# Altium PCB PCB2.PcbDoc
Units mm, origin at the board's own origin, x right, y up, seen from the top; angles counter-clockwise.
Board outline 67.61 x 64.44 mm, 2 copper layers (Top Layer, Bottom Layer); 17 components, 18 nets, 58 pads, 0 vias.
Unrouted connection lines stored in the file: 2.
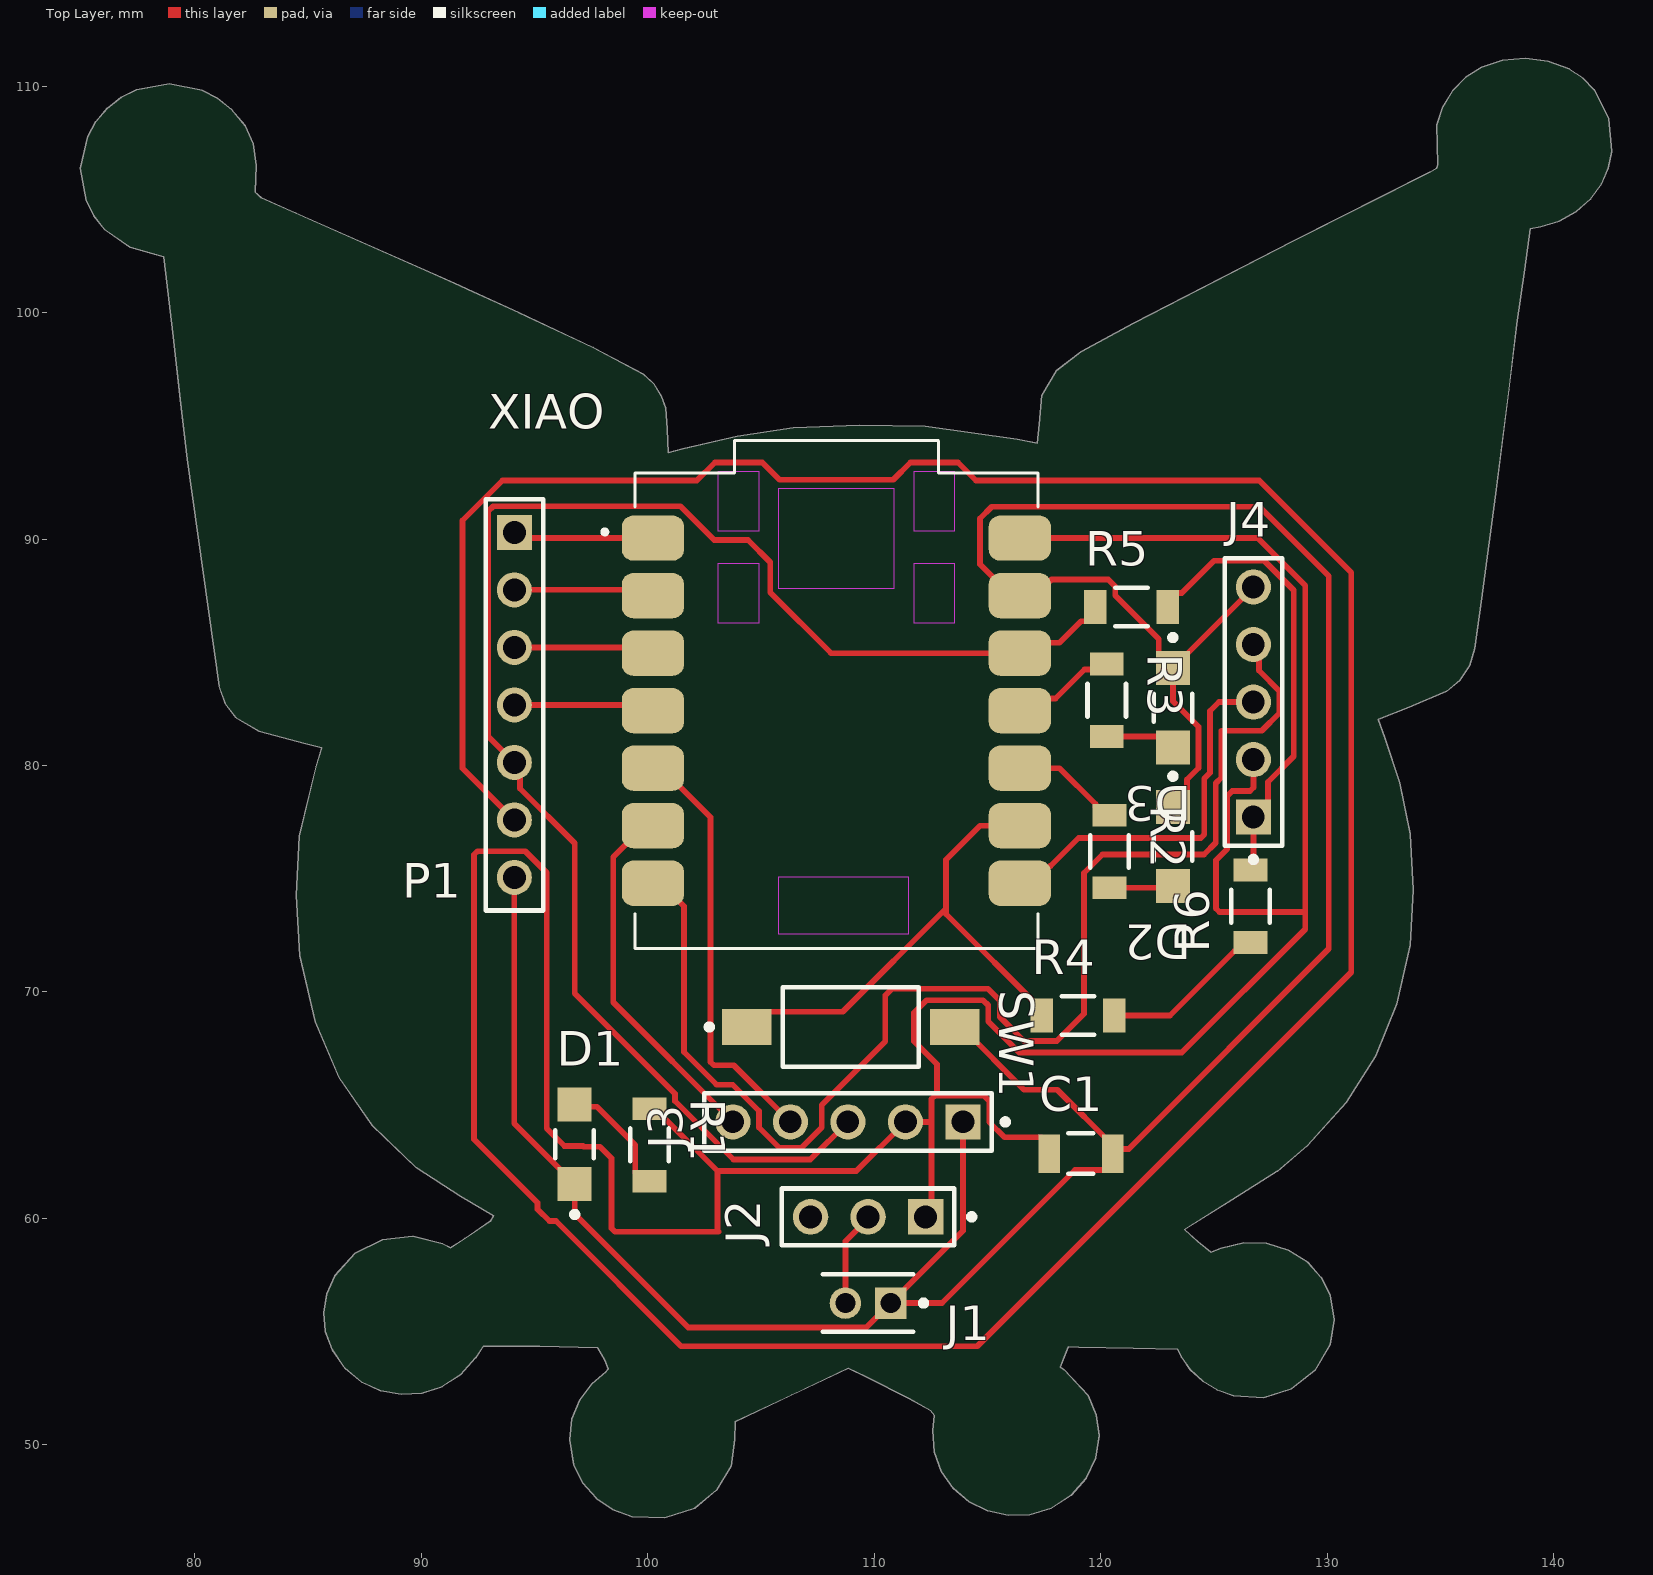
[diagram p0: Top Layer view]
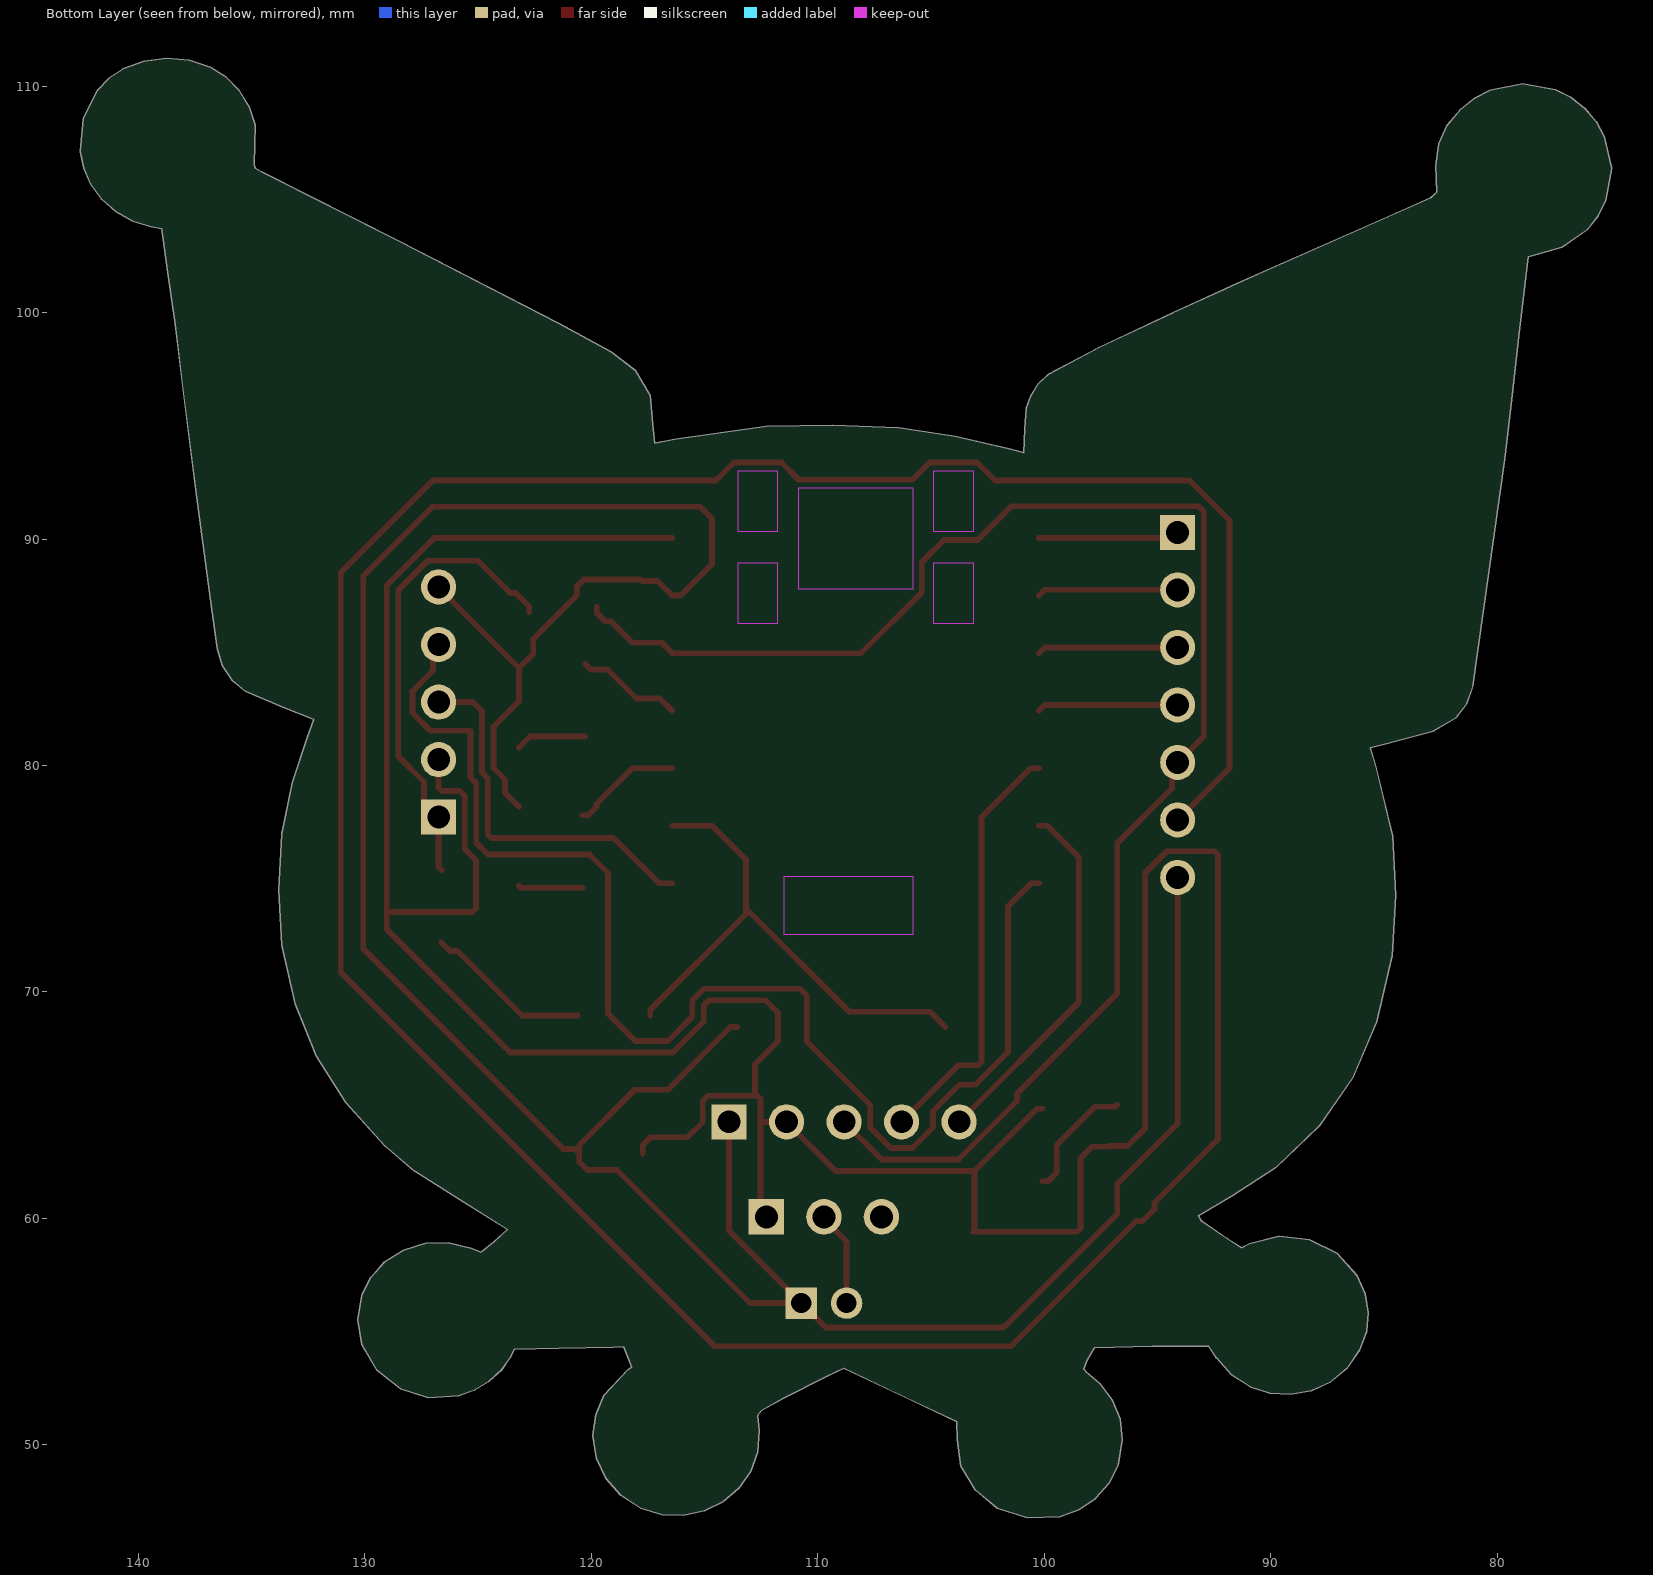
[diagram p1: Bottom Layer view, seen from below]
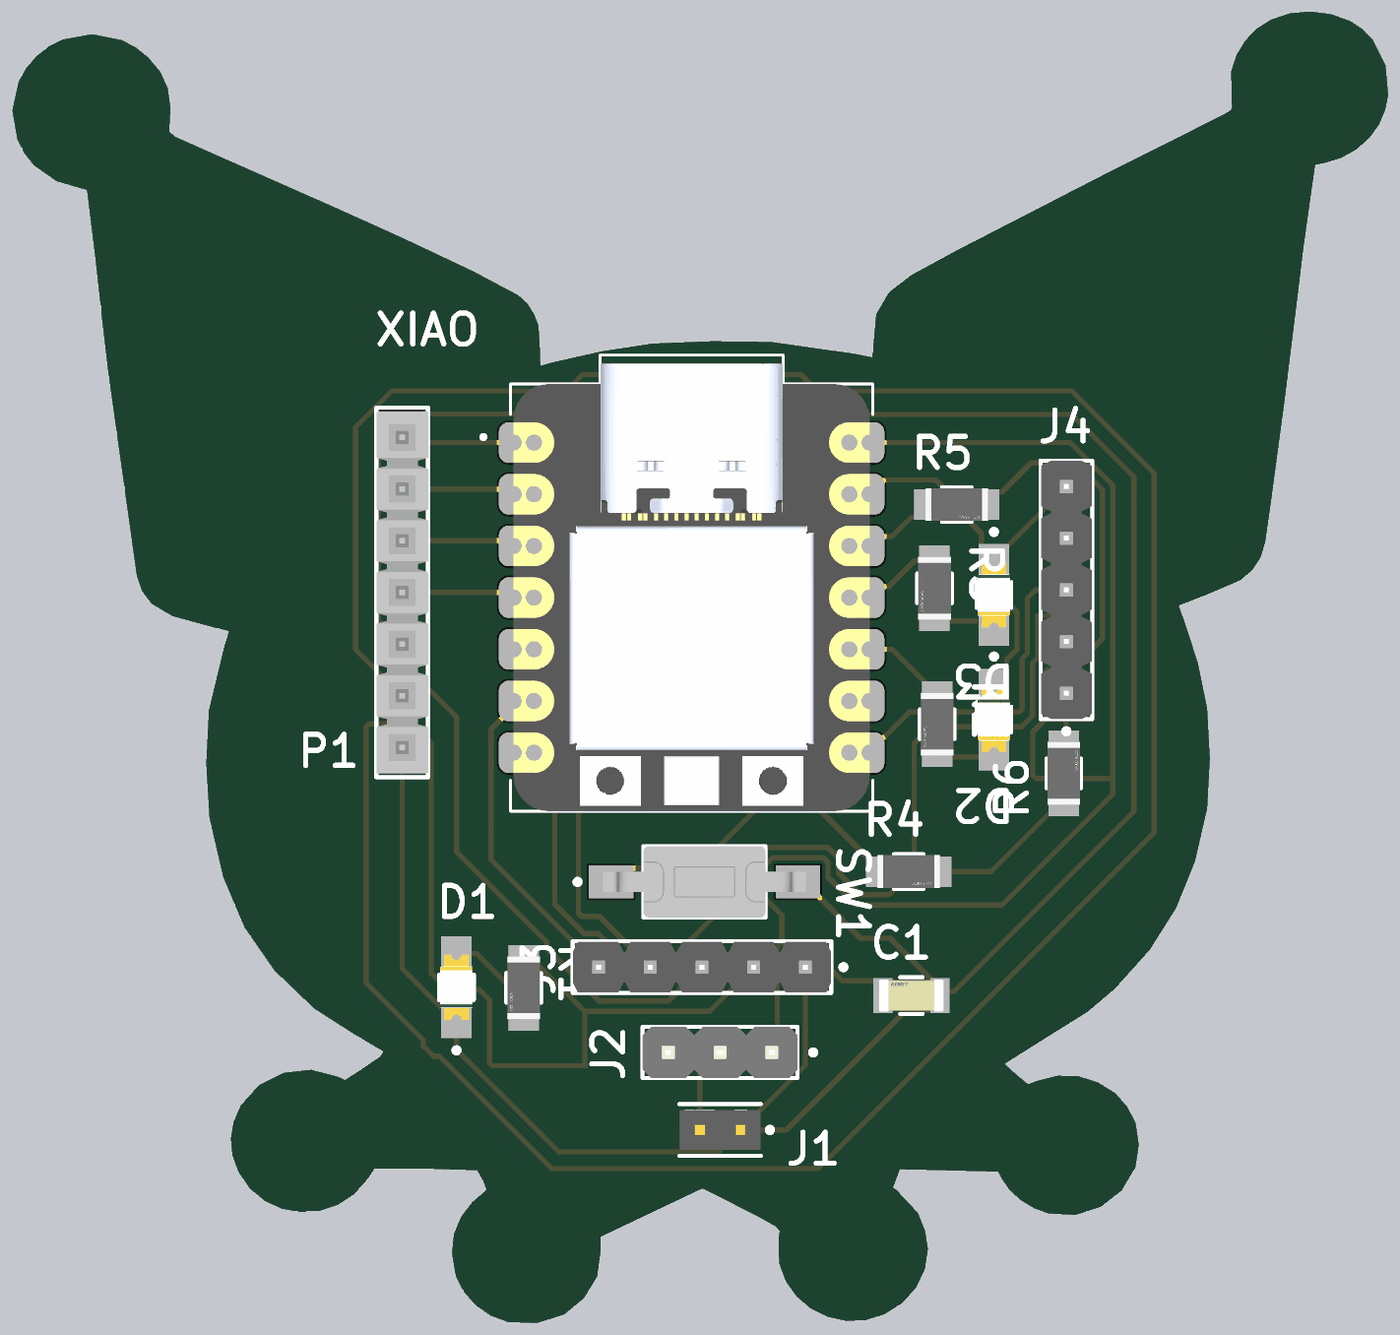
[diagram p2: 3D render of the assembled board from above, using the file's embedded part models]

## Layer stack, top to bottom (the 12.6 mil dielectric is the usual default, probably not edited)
Top Solder: solder mask 0.0102, Solder Resist, Dk 3.5
Top Layer: signal copper 0.0356
Dielectric 1: dielectric 0.32, FR-4, Dk 4.8
Bottom Layer: signal copper 0.0356
Bottom Solder: solder mask 0.0102, Solder Resist, Dk 3.5

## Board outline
86.065,54.199 86.633,53.379 87.363,52.775 88.206,52.389 89.114,52.226 90.036,52.287 90.923,52.575 91.727,53.093 92.397,53.844 92.749,54.364 95.221,54.364 97.798,54.283 98.098,53.75 98.248,53.349 98.159,53.228 97.542,52.701 96.998,51.982 96.65,51.147 96.557,50.23 96.731,49.113 97.133,48.318 97.723,47.649 98.462,47.14 99.315,46.823 99.316,46.818 100.748,46.779 102.073,47.198 103.043,48.004 103.684,49.063 103.849,50.236 103.862,51.017 106.358,52.204 108.854,53.391 109.629,53.013 111.55,52.033 112.486,51.515 112.66,51.299 112.583,50.641 112.647,49.682 112.965,48.819 113.493,48.08 114.189,47.492 115.012,47.084 115.92,46.883 116.869,46.916 117.819,47.21 118.697,47.773 119.365,48.529 119.791,49.426 119.942,50.416 119.797,51.317 119.451,52.177 118.382,53.322 118.223,53.428 118.391,53.878 118.56,54.329 119.029,54.321 121.448,54.262 123.397,54.214 123.568,53.88 123.959,53.318 124.505,52.82 125.156,52.422 125.862,52.161 127.193,52.087 128.437,52.487 129.463,53.291 130.14,54.43 130.306,55.524 130.145,56.612 129.734,57.394 129.15,58.067 128.298,58.589 127.318,58.909 126.328,58.924 125.313,58.674 124.867,58.502 124.286,58.979 123.704,59.51 125.79,60.824 127.797,62.075 129.139,63.218 130.845,65.12 132.141,67.174 133.067,69.463 133.667,72.071 133.797,74.51 133.665,76.974 133.202,79.239 132.545,81.24 132.263,82.036 133.621,82.564 135.275,83.27 135.864,83.761 136.299,84.414 136.521,85.168 136.834,87.385 137.479,92.18 138.032,96.623 138.379,99.486 138.718,101.915 138.971,103.696 139.434,103.787 140.249,104.034 140.998,104.454 141.635,105.013 142.116,105.681 142.413,106.385 142.56,107.117 142.434,108.567 141.792,109.843 141.293,110.358 140.685,110.76 139.753,111.097 138.743,111.223 137.738,111.137 136.823,110.837 136.115,110.388 135.538,109.797 135.109,109.089 134.849,108.288 134.885,106.529 134.843,106.383 134.53,106.19 128.526,103.173 121.448,99.529 119.138,98.276 118.037,97.43 117.4,96.343 117.288,95.076 117.208,94.228 116.319,94.407 112.25,94.983 109.368,95.022 106.432,94.908 103.951,94.533 101.558,93.996 100.898,93.814 100.864,94.842 100.803,95.794 100.595,96.328 100.274,96.851 99.804,97.283 97.588,98.462 94.323,100.003 92.291,100.927 91.463,101.296 90.529,101.715 84.451,104.4 82.932,105.077 82.656,105.327 82.719,106.509 82.582,107.459 82.223,108.253 81.62,108.972 81.001,109.465 80.323,109.819 78.871,110.112 77.422,109.849 76.749,109.508 76.136,109.028 75.63,108.438 75.263,107.785 74.949,106.369 75.198,104.942 75.534,104.277 76.013,103.671 77.131,102.889 78.305,102.549 78.618,102.465 79.052,98.927 79.354,96.162 79.662,93.529 81.067,83.504 81.335,82.731 81.802,82.121 82.825,81.518 84.896,80.952 85.601,80.786 85.35,79.949 84.608,76.876 84.479,74.274 84.638,71.609 85.319,68.683 86.366,66.215 87.837,64.099 89.791,62.23 91.74,60.981 93.195,60.121 93.039,59.868 91.923,59.113 91.291,58.706 90.95,58.872 89.629,59.218 88.282,59.066 87.076,58.465 86.177,57.465 85.824,56.66 85.688,55.838 85.768,55.012

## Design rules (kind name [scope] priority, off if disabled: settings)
Clearance [All] p1: gap=0.254 ignorepadtopadclearanceinfootprint=FALSE
PolygonConnect [All] p1: connectstyle=Relief reliefconductorwidth=0.254 reliefentries=4 polygonreliefangle="90 Angle" airgapwidth=0.254
RoutingVias [All] p1: holewidth=0.711 width=1.27 viastyle="Through Hole" minholewidth=0.711 minwidth=1.27 maxholewidth=0.711 maxwidth=1.27
SolderMaskExpansion [All] p1: expansion=0.102 istentingtop=FALSE
SupplyNets "Schematic Supply Nets_1" [InNet('GND')] p1: voltage=0.000
SupplyNets "Schematic Supply Nets" [InNet('VCC')] p2: voltage=0.000
Width [All] p1: maxlimit=0.5 minlimit=0.5 preferedwidth=0.5 minimp=50.000000 maximp=50.000000 favimp=50.000000
30 further rules are at their usual default settings.

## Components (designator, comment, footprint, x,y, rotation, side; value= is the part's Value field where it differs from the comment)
C1 "." FP-C1206C-EB-MFG 119.129,62.865 r0 top value="100 pF"
D1 "LED" FP-LTST-C150KSKT-MFG 96.774,63.274 r90 top
D2 "LED_1" FP-LTST-C150KSKT-MFG 123.19,76.426 r270 top
D3 "LED_2" FP-LTST-C150KSKT-MFG 123.19,82.55 r270 top
J1 "POWER" FP-TMM-102-01-L-S-MFG 109.728,56.261 r180 top
J2 "SWITCH" FP-PR20203VBNN-MFG 109.728,60.071 r180 top
J3 "I2C" FP-90120-0125-MFG 108.839,64.262 r180 top
J4 "TX-RX" FP-90120-0125-MFG 126.746,82.804 r90 top
P1 "OUTPUTS" SMTC-TSW-107-05-X-S 94.107,90.297 r270 top
R1 "." FP-AC1206-MFG 100.076,63.246 r270 top value=2.21KΩ
R2 "." FP-AC1206-MFG 120.396,76.2 r270 top value=2.21KΩ
R3 "." FP-AC1206-MFG 120.269,82.88 r270 top value=2.21KΩ
R4 "." FP-AC1206-MFG 118.999,68.961 r0 top value=2.21KΩ
R5 "." FP-AC1206-MFG 121.361,86.995 r0 top value=2.21KΩ
R6 "." FP-AC1206-MFG 126.619,73.787 r90 top value=2.21KΩ
SW1 "BUTTON" TECO-FSMSM-2_V 108.966,68.453 r0 top
XIAO "102010428" MODULE_102010428 108.331,82.423 r0 top

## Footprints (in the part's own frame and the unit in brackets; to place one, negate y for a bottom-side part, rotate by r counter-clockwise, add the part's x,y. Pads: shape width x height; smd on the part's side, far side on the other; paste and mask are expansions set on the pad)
FP-90120-0125-MFG [mm]
  rect 1.55x1.55 hole 1 paste-2539.97 mask+0: 1(-5.08,0)
  round 1.55 hole 1 paste-2539.97 mask+0: 2(-2.54,0) 3(0,0) 4(2.54,0) 5(5.08,0)
  silkscreen extent -7.07,-1.27 6.35,1.27, body extent -6.45,-1.37 6.45,1.37, height 0.25
FP-AC1206-MFG [mm]
  rect 1x1.5 smd paste+0 mask+0: 1(-1.6,0) 2(1.6,0)
  silkscreen extent -0.72,-0.85 0.72,0.85, body extent -2.2,-0.95 2.2,0.95, height 0.25
FP-C1206C-EB-MFG [mm]
  rect 0.95x1.7 smd paste+0 mask+0: 1(-1.4,0) 2(1.4,0)
  silkscreen extent -0.55,-0.9 0.55,0.9, body extent -2,-1 2,1, height 0.25
FP-LTST-C150KSKT-MFG [mm]
  rect 1.5x1.5 smd paste+0 mask+0: 1(-1.75,0) 2(1.75,0)
  silkscreen extent -3.22,-0.85 0.63,0.85, body extent -2.6,-0.95 2.6,0.95, height 0.25
FP-PR20203VBNN-MFG [mm]
  rect 1.57x1.57 hole 1.02 paste-2539.97 mask+0: 1(-2.54,0)
  round 1.57 hole 1.02 paste-2539.97 mask+0: 2(0,0) 3(2.54,0)
  silkscreen extent -4.7,-1.25 3.81,1.25, body extent -3.91,-1.35 3.91,1.35, height 0.25
FP-TMM-102-01-L-S-MFG [mm]
  rect 1.39x1.39 hole 0.89 paste-2539.97 mask+0: 1(-1,0)
  round 1.39 hole 0.89 paste-2539.97 mask+0: 2(1,0)
  silkscreen extent -2.58,-1.28 2,1.28, body extent -2.1,-1.15 2.1,1.15, height 0.25
MODULE_102010428 [mm]
  rrect50% 2.75x2 smd: 1(-8.1,7.62) 2(-8.1,5.08) 3(-8.1,2.54) 4(-8.1,0) 5(-8.1,-2.54) 6(-8.1,-5.08) 7(-8.1,-7.62) 8(8.1,-7.62) 9(8.1,-5.08) 10(8.1,-2.54) 11(8.1,0) 12(8.1,2.54) 13(8.1,5.08) 14(8.1,7.62)
  Keep-Out Layer region: 3.175,-9.865 -2.54,-9.865 -2.54,-7.325 3.175,-7.325
  Keep-Out Layer region: -3.429,7.915 -5.207,7.915 -5.207,10.582 -3.429,10.582
  Keep-Out Layer region: -3.429,3.851 -5.207,3.851 -5.207,6.518 -3.429,6.518
  Keep-Out Layer region: 5.207,3.851 3.429,3.851 3.429,6.518 5.207,6.518
  Keep-Out Layer region: 5.207,7.915 3.429,7.915 3.429,10.582 5.207,10.582
  Keep-Out Layer region: 2.54,5.375 -2.54,5.375 -2.54,9.82 2.54,9.82
  silkscreen extent -10.33,-10.5 8.9,11.92, body extent -8.75,-10.5 8.75,11.5, height 4.41
SMTC-TSW-107-05-X-S [mm] ".025 SQ Post Terminal Strip Assembly, 1x7 Pins, Vertical, 2.54mm Pitch, Male"
  rect 1.55x1.55 hole 1.02: 1(0,0)
  round 1.55 hole 1.02: 2(2.54,0) 3(5.08,0) 4(7.62,0) 5(10.16,0) 6(12.7,0) 7(15.24,0)
  silkscreen extent -1.46,-1.27 16.7,1.27, body extent -1.27,-1.27 16.51,1.27, height 5.21
TECO-FSMSM-2_V [mm] "SMD, 2-Leads, Body 6x3.5mm, Pitch 9.19mm"
  rect 2.2x1.6 smd: 1(-4.595,0)
  rect 2.18x1.6 smd: 2(4.595,0)
  silkscreen extent -6.37,-1.75 3,1.75, body extent -4.98,-1.75 4.98,1.75, height 4.4

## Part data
C1: library part CMP-03020-023751-1, "C1206 100 pF X8R 10.00% 50 V", Capacitance="100 pF", Manufacturer=KEMET, Manufacturer Part Number=C1206C101K5HACTU, Package=C1206C-EB, Temperature="-55°C to +150°C", Temperature Characteristic=X8R, Temperature Coefficient=15%, Temperature Range High=+150°C, Temperature Range Low=-55°C, Tolerance=0.1, Voltage Rating="50 V"
D1 D2 D3: library part CMP-2000-06618-2, "LED YELLOW CLEAR 1206 SMD", Case Code (Imperial)=1206, Case Code (Metric)=3216, Color=Yellow, Forward Current=30mA, Forward Voltage=2.4V, Lens Color=Colorless, Max Operating Temperature=85°C, Min Operating Temperature=-55°C, Package Quantity=1, Power Dissipation=75mW, Reverse Voltage=5V, Test Current=20mA
J1: library part CMP-02766-001606-1, "CONN HEADER VERT 2POS 2MM", Housing Color=Black, Max Current Rating=3.9A, Max Operating Temperature=125°C, Max Voltage Rating (AC)=500V, Min Operating Temperature=-55°C
J2: library part CMP-77940-000002-1, "CONN HEADER VERT 3POS 2.54MM", Current Rating=3A, Manufacturer="Metz Connect", Manufacturer Part Number=PR20203VBNN, Temperature="-40°C to +105°C", Temperature Range High=+105°C, Temperature Range Low=-40°C
J3 J4: library part CMP-00257-00655425-1, "90120-0125 2.54mm Pitch C-Grid III Header, Single Row, Vertical, 5 Circuits, Tin (Sn) Plating", Contact Resistance=20mΩ, Current Rating=3A, Housing Color=Black, Manufacturer Lifecycle Status=ACTIVE, Max Operating Temperature=125°C, Max Voltage Rating (DC)=350.35kV, Min Operating Temperature=-55°C, Voltage Rating=350V
P1: library part CMP-1024-00402-1, "0.025\" SQ Post Header, Through-hole, Vertical, -55 to 125 degC, 2.54 mm Pitch, 7-Pin, Male, RoHS", Manufacturer=Samtec, PartNumber=TSW-107-05-F-S, Temperature Range="-55 to 125 degC"
R1 R2 R3 R4 R5 R6: library part CMP-03412-032679-1, "RES SMD 2.21K OHM 1% 1/4W 1206", Manufacturer=Yageo, Manufacturer Part Number=AC1206FR-072K21L, Package=AC1206, Power Rating=0.25W, Resistance=2.21KΩ, Temperature="-55°C to +155°C", Temperature Range High=+155°C, Temperature Range Low=-55°C, Tolerance=0.01, Voltage Rating=200V
SW1: library part CMP-2000-07511-1, "FSMSM Push Button Switch, 50 mA, -35 to 85 degC, 2-Pin SMD, RoHS, Bulk", Case\/Package=SMD/SMT, Contact Current Rating=50mA, Contact Resistance=100mOhm, Manufacturer="TE Connectivity", Max Operating Temperature=85degC, Max Voltage Rating (DC)=12V, Min Operating Temperature=-35degC, Operating Force=180gf, Package Description="2-Pin Surface Mount Device, Body 6 x 3.5 mm, Pitch 9.19 mm", Package Quantity=1000, Package Reference=FSMSM, Voltage Rating (DC)=24V
XIAO: "RP2040 XIAO RP2040 series ARMÂ® CortexÂ®-M0+ MCU 32-Bit Embedded Evaluation Board", Package=None

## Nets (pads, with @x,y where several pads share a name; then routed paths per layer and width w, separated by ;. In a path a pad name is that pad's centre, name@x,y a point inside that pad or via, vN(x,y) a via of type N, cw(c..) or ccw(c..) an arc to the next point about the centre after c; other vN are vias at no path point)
3V3: J3.3 J4.1 P1.5 R4.2 R5.1 R5.2 R6.1 R6.2 XIAO.12 | length 98.1
  Top Layer w0.254: J3.3 107.175,62.598 103.788,62.598 101.207,65.179 101.207,65.504 96.774,69.937 96.774,76.565 94.355,78.984 94.355,79.889 P1.5 92.951,81.293 92.951,91.23 93.174,91.453 101.442,91.453 102.938,89.957 104.425,89.957 105.41,88.972 105.41,87.64 108.087,84.963 XIAO.12 116.889,85.421 118.187,85.421 119.138,86.372 119.388,86.372 119.761,86.745 R5.1 ; R4.2 123.063,68.961 125.916,71.814 126.246,71.814 R6.1 ; R5.2@122.747,86.781 122.747,87.031 123.334,87.618 123.584,87.618 125.006,89.04 127.225,89.04 128.524,87.741 128.524,80.407 127.394,79.277 127.394,78.372 J4.1 126.746,75.514 R6.2
5V: C1.1 J2.1 J3.2 J4.2 P1.6 R1.1 XIAO.14 | length 258.3
  Top Layer w0.254: P1.6 91.821,79.883 91.821,90.818 93.586,92.583 102.163,92.583 102.966,93.386 105.06,93.386 105.822,92.624 110.84,92.624 111.602,93.386 113.696,93.386 114.499,92.583 127,92.583 131.064,88.519 131.064,70.866 114.554,54.356 101.473,54.356 95.944,59.885 95.656,59.885 95.135,60.406 95.135,60.694 92.329,63.5 92.329,76.064 92.478,76.213 94.586,76.213 95.536,75.263 95.536,63.976 96.317,63.195 97.142,63.195 97.174,63.163 97.892,63.163 98.401,62.654 98.401,59.562 98.55,59.413 103.124,59.413 103.082,59.455 103.082,62.09 ; R1.1 100.326,64.846 103.082,62.09 ; J2.1 112.535,60.338 112.535,64.262 ; XIAO.14 126.94,90.043 129.032,87.951 129.032,72.771 123.583,67.322 116.402,67.322 115.032,68.692 115.032,69.411 114.809,69.634 112.313,69.634 111.76,69.081 111.76,67.825 112.776,66.809 112.776,65.418 ; C1.1 117.729,63.24 117.381,63.588 115.749,63.588 115.075,64.262 115.075,65.195 114.852,65.418 112.776,65.418 ; J4.2 126.746,79.029 126.597,78.88 125.813,78.88 125.59,78.657 125.59,76.314 125.095,75.819 125.095,73.682 125.244,73.533 129.032,73.533 ; 103.082,62.09 109.207,62.09 J3.2 112.535,64.262 ; 112.535,64.262 112.535,65.269 112.684,65.418 112.776,65.418
A0: P1.1 XIAO.1 | length 6.2
  Top Layer w0.254: P1.1 94.361,90.043 XIAO.1
A1: P1.2 XIAO.2 | length 6.2
  Top Layer w0.254: P1.2 99.977,87.757 XIAO.2
A2: P1.3 XIAO.3 | length 6.2
  Top Layer w0.254: P1.3 99.977,85.217 XIAO.3
A3: P1.4 XIAO.4 | length 6.2
  Top Layer w0.254: P1.4 99.977,82.677 XIAO.4
D8: R4.1 SW1.1 XIAO.9 | length 23.5
  Top Layer w0.254: SW1.1 105.044,69.126 108.613,69.126 113.169,73.683 ; XIAO.9 114.675,77.343 113.169,75.837 113.169,73.683 ; R4.1 117.399,69.211 113.169,73.441 113.169,73.683
D9: R2.1 XIAO.10 | length 4.9
  Top Layer w0.254: XIAO.10 118.187,79.883 119.773,78.297 119.773,78.173 120.146,77.8 R2.1
D10: R3.1 XIAO.11 | length 4.7
  Top Layer w0.254: XIAO.11 116.965,82.957 118.009,82.957 119.287,84.235 120.024,84.235 R3.1
GND: C1.2 D1.1 D2.1 D3.1 J1.1 J3.1 J4.5 P1.7 SW1.2 XIAO.13 | length 136.4
  Top Layer w0.254: P1.7 94.107,64.191 D1.1 96.774,60.198 101.787,55.185 109.652,55.185 J1.1 ; SW1.2 113.851,68.453 116.62,65.684 118.085,65.684 120.529,63.24 C1.2 ; J3.1 113.919,59.452 J1.1 ; D2.1 123.813,78.799 123.813,79.384 124.321,79.892 124.321,81.708 123.19,82.839 D3.1 ; J4.5 126.746,87.856 D3.1 ; J1.1 112.989,56.261 118.87,62.142 120.181,62.142 120.529,62.49 C1.2 ; C1.2 120.734,63.07 121.236,63.07 130.07,71.904 130.07,88.37 127.016,91.424 115.191,91.424 114.675,90.908 114.675,88.884 116.056,87.503 XIAO.13 117.074,88.146 117.761,88.146 117.828,88.212 120.333,88.212 120.642,87.903 120.642,87.511 122.567,85.586 122.567,84.923 D3.1
NetD1_2: D1.2 R1.2 | length 5.4
  Top Layer w0.254: D1.2 96.867,64.931 97.756,64.931 99.453,63.234 99.453,62.019 99.826,61.646 R1.2
NetD2_2: D2.2 R2.2 | length 2.8
  Top Layer w0.254: R2.2 123.114,74.6 D2.2
NetD3_2: D3.2 R3.2 | length 3.1
  Top Layer w0.254: R3.2 122.71,81.28 D3.2
RX: J4.3 XIAO.8 | length 16.7
  Top Layer w0.254: XIAO.8 117.008,74.803 117.766,75.561 117.786,75.561 119.028,76.803 124.425,76.803 124.574,76.952 124.574,79.427 124.829,79.682 124.829,82.411 125.222,82.804 J4.3
SCL: J3.5 XIAO.6 | length 16.2
  Top Layer w0.254: XIAO.6 99.856,77.343 98.475,75.962 98.475,69.546 J3.5
SDA: J3.4 XIAO.5 | length 18.9
  Top Layer w0.254: XIAO.5 100.606,79.883 102.773,77.716 102.773,66.913 102.922,66.764 103.797,66.764 J3.4
TX: J4.4 XIAO.7 | length 58.7
  Top Layer w0.254: XIAO.7 100.578,74.803 101.6,73.781 101.6,67.348 103.041,65.908 103.748,65.908 104.915,64.741 104.915,64.011 105.82,63.106 106.778,63.106 107.683,64.011 107.683,65.004 110.49,67.811 110.49,69.85 110.782,70.142 115.019,70.142 115.54,69.621 115.54,68.903 116.613,67.83 118.057,67.83 119.265,69.038 119.265,75.258 120.08,76.073 124.563,76.073 125.082,76.592 125.082,79.216 125.337,79.471 125.337,81.534 127.111,81.534 127.902,82.325 127.902,83.283 126.994,84.191 126.994,85.096 J4.4
VCC: J1.2 J2.2 | length 4.2
  Top Layer w0.254: J1.2 108.728,58.987 109.728,59.987 J2.2
pads on no net: J2.3

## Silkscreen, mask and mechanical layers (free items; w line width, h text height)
Mechanical 2:
  drawing of 200 lines, arcs and shapes, not listed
